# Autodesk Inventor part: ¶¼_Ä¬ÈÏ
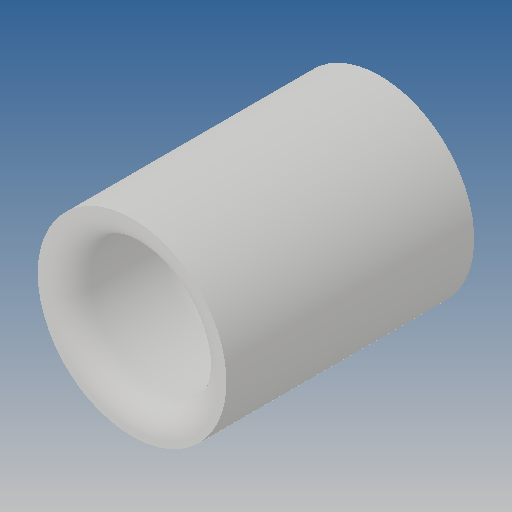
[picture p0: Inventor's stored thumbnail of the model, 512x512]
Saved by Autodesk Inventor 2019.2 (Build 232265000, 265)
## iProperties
Created: 2012-03
Part Number: ¶¼_Ä¬ÈÏ
Material: Ogólny
Document SubType Name: Modeling
Designer: CADENGINEERING4
Density: 1 g/cm^3
Appearance: Domyślna
Author: CADENGINEERING4
Revision Number: ÈÎºÎ
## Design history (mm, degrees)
feature "NONE"
node "Bryła1"
